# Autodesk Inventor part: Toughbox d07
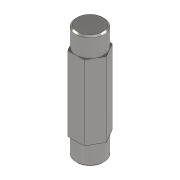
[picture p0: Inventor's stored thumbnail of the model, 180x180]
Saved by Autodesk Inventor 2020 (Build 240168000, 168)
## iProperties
Created: 2020-01
Part Number: Toughbox d07
Material: Stainless Steel
Document SubType Name: Modeling
Designer: woodk
Density: 8 g/cm^3
Appearance: Semi-Polished
Vendor: KoP
Mass: 23.162 g
Surface Area: 13.5872 cm^2
Volume: 2.89525 cm^3
Author: woodk
Revision Number: ANY
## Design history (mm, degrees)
feature "Cut-Extrude3"
body "Solid1"
